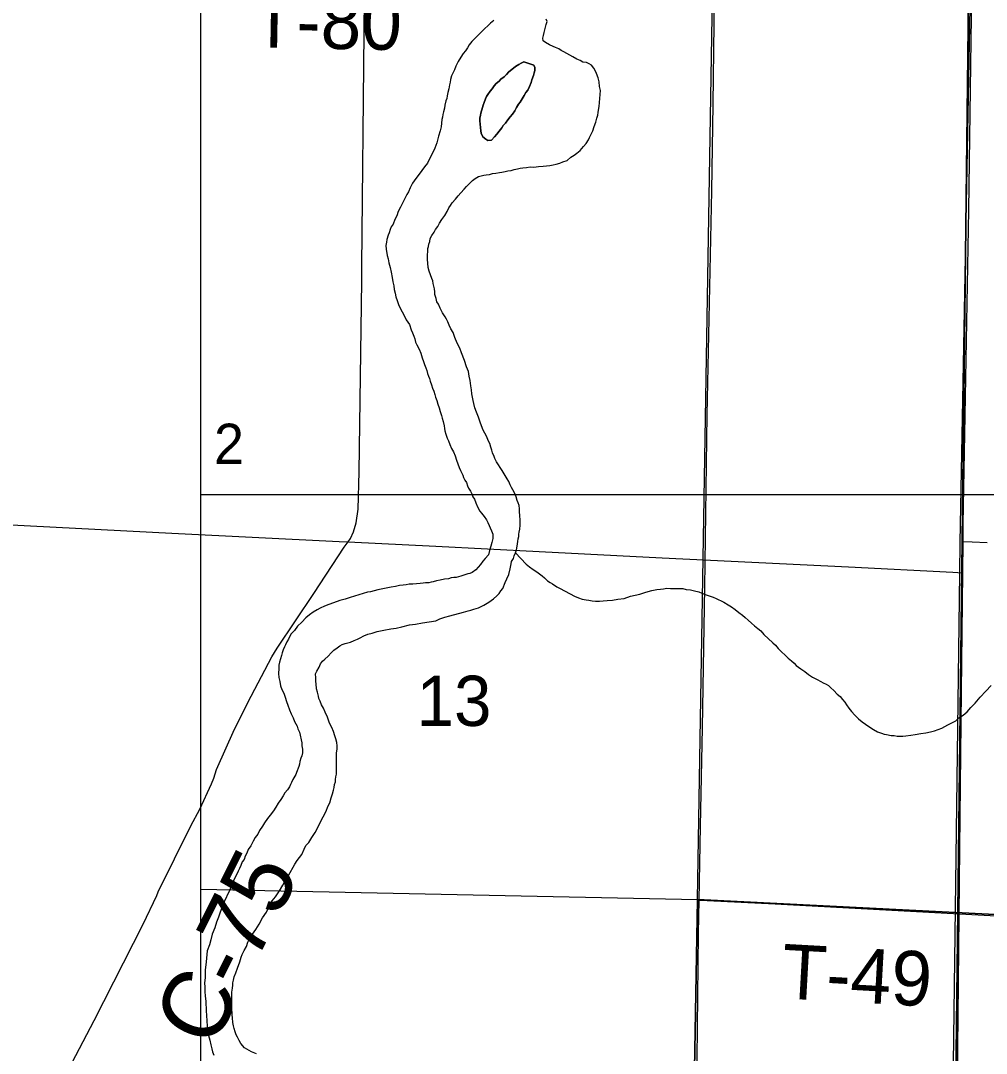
# Model space of a CAD drawing. Extents: x 0 to 68, y 0 to 52.9.
# Drawn here: x 42.06 to 43.122, y 34.125 to 35.26 of the extents above; entities that cross this region are included whole.
import ezdxf

# ---------------------------------------------------------------- set-up
doc = ezdxf.new("R2010")
doc.units = 0
for name, color, linetype in [('Default', 7, 'Continuous'), ('GM_X_County_Road', 7, 'Continuous'), ('GM_X_County_Road_Text', 7, 'Continuous'), ('GM_X_Minor_River', 7, 'Continuous'), ('GM_X_Township', 7, 'Continuous'), ('GM_X_Township_Road', 7, 'Continuous'), ('GM_X_Township_Road_Text', 7, 'Continuous')]:
    doc.layers.add(name, color=color, linetype=linetype)

msp = doc.modelspace()

# ---------------------------------------------------------------- linework, layer by layer
at = {"layer": 'Default'}
for p, q in [((42.2581, 31.1431), (42.2581, 38.5351)), ((42.2581, 34.7391), (49.6501, 34.7391))]:
    msp.add_line(p, q, dxfattribs=at)
for points in [[(43.089, 34.0291), (43.0906, 34.1657), (43.0925, 34.3503), (43.0942, 34.5226), (43.0956, 34.6532), (43.096, 34.6875), (43.0962, 34.7071), (43.0981, 34.8056), (43.1022, 35.0517), (43.1053, 35.2649), (43.1059, 35.3134), (43.1062, 35.3458), (43.1075, 35.4536), (43.1091, 35.5889), (43.1114, 35.8842), (43.1128, 36.0132), (43.1137, 36.1016), (43.1169, 36.3846), (43.1196, 36.6143), (43.12, 36.643), (43.1213, 36.7456), (43.1227, 36.8522)], [(42.2581, 34.3055), (42.8041, 34.2941), (42.7855, 33.2374), (42.2581, 33.2485)]]:
    msp.add_lwpolyline(points, dxfattribs=at)
for points in [[(41.7644, 35.3862), (43.1022, 35.3161), (43.0873, 34.0306), (43.0864, 33.9961), (41.7454, 34.0552)], [(43.1026, 35.3466), (43.6933, 35.3509), (44.3202, 35.3382), (44.3032, 34.0046), (43.0873, 34.0306), (43.1022, 35.3161)], [(42.821, 35.3089), (43.8802, 35.2907), (43.8665, 34.2714), (43.8657, 34.2406), (42.8041, 34.2941)], [(42.8041, 34.2941), (43.8657, 34.2406), (43.8561, 33.2057), (43.8558, 33.1813), (42.7855, 33.2374)]]:
    msp.add_lwpolyline(points, close=True, dxfattribs=at)
at = {"layer": 'GM_X_County_Road'}
for points in [[(42.4198, 34.6871), (42.4225, 34.6909), (42.426, 34.6983), (42.4289, 34.7082), (42.4308, 34.7233), (42.4322, 34.7643), (42.4349, 34.9736), (42.4349, 34.9899), (42.4376, 35.2473), (42.4382, 35.3252), (42.4389, 35.3376), (42.4396, 35.3493)], [(41.5874, 34.7233), (41.6335, 34.7225), (41.7192, 34.7213), (41.7888, 34.7191), (41.8706, 34.7152), (41.9361, 34.7118), (42.2262, 34.6969), (42.4102, 34.6875), (42.4198, 34.6871)], [(42.0801, 34.0424), (42.0847, 34.0517), (42.1085, 34.0993), (42.1406, 34.1609), (42.1946, 34.267), (42.2097, 34.2984), (42.2109, 34.3024), (42.247, 34.3749), (42.2567, 34.3933), (42.2698, 34.4213), (42.2724, 34.4273), (42.2753, 34.4371), (42.2951, 34.4811), (42.301, 34.4926), (42.3098, 34.5104), (42.336, 34.5607), (42.342, 34.5704), (42.3824, 34.6304), (42.4156, 34.6813), (42.4198, 34.6871)], [(42.4198, 34.6871), (42.5162, 34.6826), (42.6299, 34.6764), (42.7651, 34.6697), (42.9699, 34.6599), (43.0846, 34.6538), (43.0956, 34.6532)]]:
    msp.add_lwpolyline(points, dxfattribs=at)
at = {"layer": 'GM_X_Minor_River'}
for points in [[(42.637, 35.2362), (42.6345, 35.2378), (42.634, 35.2408), (42.6346, 35.2438), (42.6356, 35.2473), (42.6377, 35.2558), (42.6387, 35.2593), (42.6378, 35.2618)], [(42.58, 35.2604), (42.5764, 35.2575), (42.5734, 35.2545), (42.5703, 35.2515), (42.5673, 35.2485), (42.5648, 35.246), (42.5622, 35.2435), (42.5587, 35.2401), (42.5561, 35.2371), (42.5531, 35.2336), (42.551, 35.2301), (42.549, 35.2271), (42.5465, 35.2241), (42.5439, 35.2201), (42.5408, 35.2151), (42.5383, 35.2101), (42.5367, 35.2061), (42.5352, 35.2026), (42.5337, 35.1996), (42.5326, 35.1956), (42.5321, 35.1926), (42.5315, 35.1896), (42.5305, 35.1851), (42.5295, 35.1811), (42.5289, 35.1776), (42.5284, 35.1746), (42.5274, 35.1721), (42.5263, 35.1671), (42.5258, 35.164), (42.5247, 35.16), (42.5242, 35.157), (42.5237, 35.154), (42.5231, 35.1515), (42.5226, 35.1475), (42.5221, 35.1435), (42.521, 35.139), (42.5194, 35.133), (42.5174, 35.126), (42.5153, 35.1199), (42.5071, 35.1035), (42.504, 35.0995), (42.501, 35.0955), (42.4979, 35.0915), (42.4944, 35.0865), (42.4908, 35.0815), (42.4882, 35.0765), (42.4862, 35.072), (42.4846, 35.069), (42.4826, 35.0655), (42.4805, 35.061), (42.4775, 35.055), (42.4749, 35.0505), (42.4734, 35.0455), (42.4713, 35.0415), (42.4693, 35.0365), (42.4672, 35.0335), (42.4662, 35.0305), (42.4651, 35.027), (42.4641, 35.0245), (42.4626, 35.0195), (42.462, 35.0165), (42.4615, 35.013), (42.4619, 35.009), (42.4629, 35.0019), (42.4639, 34.9984), (42.4648, 34.9939), (42.4663, 34.9888), (42.4672, 34.9838), (42.4682, 34.9778), (42.4691, 34.9732)], [(42.5129, 34.9743), (42.5119, 34.9768), (42.5104, 34.9809), (42.5089, 34.9849), (42.508, 34.9889), (42.5075, 34.9934), (42.5071, 34.9975), (42.5071, 35), (42.5071, 35.003), (42.5076, 35.006), (42.5077, 35.0095), (42.5082, 35.012), (42.5087, 35.0145), (42.5098, 35.0175), (42.5103, 35.0205), (42.5118, 35.024), (42.5144, 35.0275), (42.5159, 35.0305), (42.5185, 35.034), (42.5205, 35.0375), (42.5231, 35.0415), (42.5261, 35.046), (42.5287, 35.0505), (42.5307, 35.0545), (42.5323, 35.057), (42.5343, 35.06), (42.5378, 35.064), (42.5409, 35.0674), (42.5439, 35.0709), (42.5475, 35.0749), (42.55, 35.0779), (42.5526, 35.0804), (42.5566, 35.0844), (42.5597, 35.0868), (42.5632, 35.0888), (42.5693, 35.0903), (42.5718, 35.0907), (42.5753, 35.0912), (42.5788, 35.0922), (42.5823, 35.0926), (42.5864, 35.0931), (42.5889, 35.0936), (42.5924, 35.0945), (42.5954, 35.095), (42.599, 35.0955), (42.6025, 35.0964), (42.606, 35.0974), (42.609, 35.0979), (42.612, 35.0983), (42.6161, 35.0988), (42.6201, 35.0993), (42.6241, 35.0992), (42.6291, 35.0997), (42.6342, 35.1001), (42.6382, 35.1006), (42.6417, 35.1011), (42.6452, 35.1015), (42.6488, 35.1025), (42.6528, 35.1034), (42.6558, 35.1049), (42.6609, 35.1064), (42.6649, 35.1099), (42.6685, 35.1123), (42.6715, 35.1143), (42.675, 35.1173), (42.6786, 35.1218), (42.6816, 35.1252), (42.6842, 35.1292), (42.6852, 35.1317), (42.6873, 35.1352), (42.6888, 35.1392), (42.6904, 35.1437), (42.6924, 35.1487), (42.6935, 35.1528), (42.6945, 35.1563), (42.695, 35.1593), (42.6951, 35.1618), (42.6961, 35.1658), (42.6972, 35.1788), (42.6973, 35.1834), (42.6963, 35.1879), (42.6959, 35.1929), (42.6949, 35.1974), (42.693, 35.202), (42.692, 35.2045), (42.69, 35.208), (42.6875, 35.2111), (42.685, 35.2126), (42.682, 35.2142), (42.678, 35.2147), (42.675, 35.2162), (42.6715, 35.2178), (42.667, 35.2203), (42.6605, 35.2239), (42.657, 35.226), (42.654, 35.2275), (42.6515, 35.229), (42.648, 35.2306), (42.6455, 35.2316), (42.6415, 35.2337), (42.637, 35.2362)], [(42.6242, 35.2112), (42.6132, 35.2149), (42.6102, 35.2134), (42.6076, 35.2119), (42.6041, 35.2099), (42.6, 35.2065), (42.5965, 35.204), (42.594, 35.201), (42.5914, 35.1985), (42.5879, 35.196), (42.5859, 35.1936), (42.5828, 35.1911), (42.5803, 35.1886), (42.5782, 35.1851), (42.5762, 35.1826), (42.5737, 35.1791), (42.5721, 35.1766), (42.5711, 35.1741), (42.5695, 35.1701), (42.5685, 35.1671), (42.5675, 35.1646), (42.5659, 35.1586), (42.5654, 35.1561), (42.5649, 35.1531), (42.5648, 35.1501), (42.5657, 35.139), (42.5662, 35.1365), (42.5682, 35.1325), (42.5712, 35.1299)], [(42.6242, 35.2112), (42.6252, 35.2087), (42.6252, 35.2052), (42.6246, 35.2027), (42.6236, 35.1997), (42.622, 35.1952), (42.621, 35.1922), (42.6195, 35.1877), (42.6174, 35.1837), (42.6154, 35.1812), (42.6133, 35.1777), (42.6113, 35.1742), (42.6092, 35.1707), (42.6072, 35.1682), (42.6052, 35.1647), (42.6031, 35.1612), (42.6006, 35.1572), (42.598, 35.1543), (42.5955, 35.1513), (42.5929, 35.1473), (42.5904, 35.1448), (42.5889, 35.1423), (42.5858, 35.1388), (42.5833, 35.1353), (42.5807, 35.1323), (42.5777, 35.1288), (42.5737, 35.1284), (42.5712, 35.1299), (42.5682, 35.1325), (42.5662, 35.1365), (42.5657, 35.139), (42.5648, 35.1501), (42.5649, 35.1531), (42.5654, 35.1561), (42.5659, 35.1586), (42.5675, 35.1646), (42.5685, 35.1671), (42.5695, 35.1701), (42.5711, 35.1741), (42.5721, 35.1766), (42.5737, 35.1791), (42.5762, 35.1826), (42.5782, 35.1851), (42.5803, 35.1886), (42.5828, 35.1911), (42.5859, 35.1936), (42.5879, 35.196), (42.5914, 35.1985), (42.594, 35.201), (42.5965, 35.204), (42.6, 35.2065), (42.6041, 35.2099), (42.6076, 35.2119), (42.6102, 35.2134), (42.6132, 35.2149), (42.6242, 35.2112)], [(42.5712, 35.1299), (42.5737, 35.1284), (42.5777, 35.1288), (42.5807, 35.1323), (42.5833, 35.1353), (42.5858, 35.1388), (42.5889, 35.1423), (42.5904, 35.1448), (42.5929, 35.1473), (42.5955, 35.1513), (42.598, 35.1543), (42.6006, 35.1572), (42.6031, 35.1612), (42.6052, 35.1647), (42.6072, 35.1682), (42.6092, 35.1707), (42.6113, 35.1742), (42.6133, 35.1777), (42.6154, 35.1812), (42.6174, 35.1837), (42.6195, 35.1877), (42.621, 35.1922), (42.622, 35.1952), (42.6236, 35.1997), (42.6246, 35.2027), (42.6252, 35.2052), (42.6252, 35.2087), (42.6242, 35.2112)], [(42.4691, 34.9732), (42.4701, 34.9687), (42.4706, 34.9647), (42.4715, 34.9607), (42.4725, 34.9566), (42.474, 34.9526), (42.4754, 34.9481), (42.4779, 34.9425), (42.4808, 34.9375), (42.4838, 34.9314), (42.4873, 34.9263), (42.4892, 34.9203), (42.4907, 34.9168), (42.4922, 34.9132), (42.4931, 34.9102), (42.4941, 34.9067), (42.4956, 34.9036), (42.498, 34.8991), (42.5, 34.8946), (42.5015, 34.8895), (42.5029, 34.8855), (42.5039, 34.882), (42.5054, 34.8784), (42.5064, 34.8754), (42.5073, 34.8724), (42.5083, 34.8694), (42.5093, 34.8668), (42.5103, 34.8638), (42.5117, 34.8598), (42.5127, 34.8563), (42.5142, 34.8527), (42.5151, 34.8492), (42.5161, 34.8462), (42.5176, 34.8426), (42.5186, 34.8386), (42.52, 34.8346), (42.521, 34.8305), (42.5224, 34.826), (42.5234, 34.823), (42.5244, 34.8195), (42.5254, 34.8149), (42.5258, 34.8119), (42.5263, 34.8094), (42.5273, 34.8054), (42.5287, 34.8013), (42.5302, 34.7983), (42.5317, 34.7943), (42.5336, 34.7897), (42.5356, 34.7862), (42.5376, 34.7816), (42.539, 34.7771), (42.5405, 34.7731), (42.542, 34.769), (42.5435, 34.7655), (42.5459, 34.7605), (42.5469, 34.7579), (42.5484, 34.7549), (42.5499, 34.7524), (42.5513, 34.7489), (42.5523, 34.7463), (42.5543, 34.7428), (42.5558, 34.7398), (42.5572, 34.7367), (42.5587, 34.7342), (42.5602, 34.7302), (42.5622, 34.7256), (42.5646, 34.7211), (42.5666, 34.7186), (42.5696, 34.715), (42.5721, 34.7115), (42.5735, 34.7084), (42.5775, 34.6994), (42.5789, 34.6958), (42.5789, 34.6933), (42.5789, 34.6908), (42.5778, 34.6863), (42.5768, 34.6823), (42.5752, 34.6778), (42.5742, 34.6728), (42.5706, 34.6688), (42.5681, 34.6658), (42.5655, 34.6623), (42.563, 34.6593), (42.5605, 34.6563), (42.5564, 34.6534), (42.5539, 34.6524), (42.5514, 34.6519), (42.5484, 34.6509), (42.5438, 34.6495), (42.5388, 34.648), (42.5363, 34.648), (42.5333, 34.6476), (42.5302, 34.6466), (42.5257, 34.6461), (42.5212, 34.6452), (42.5171, 34.6442), (42.5136, 34.6433), (42.5111, 34.6428), (42.5086, 34.6423), (42.5051, 34.6423), (42.5025, 34.6419)], [(42.479, 34.5939), (42.4875, 34.5958), (42.4941, 34.5967), (42.5016, 34.5982), (42.5092, 34.5991), (42.5162, 34.6005), (42.5207, 34.6025), (42.5263, 34.6044), (42.5318, 34.6059), (42.5469, 34.6098), (42.552, 34.6112), (42.555, 34.6122), (42.558, 34.6132), (42.5631, 34.6146), (42.5691, 34.6176), (42.5747, 34.621), (42.5798, 34.6245), (42.5833, 34.628), (42.5858, 34.6304), (42.5879, 34.6334), (42.5899, 34.6359), (42.5925, 34.6424), (42.5945, 34.6464), (42.5966, 34.6514), (42.5982, 34.6574), (42.5992, 34.663), (42.5997, 34.6655), (42.6018, 34.669), (42.6023, 34.672), (42.6039, 34.675), (42.6049, 34.6785), (42.6059, 34.6825), (42.6065, 34.6875), (42.607, 34.6905), (42.6076, 34.693), (42.6076, 34.6955), (42.6081, 34.698), (42.6086, 34.701), (42.6092, 34.7056), (42.6092, 34.7111), (42.6088, 34.7161), (42.6083, 34.7201), (42.6084, 34.7236), (42.6079, 34.7272), (42.6069, 34.7302), (42.6059, 34.7327), (42.6045, 34.7367), (42.6025, 34.7418), (42.601, 34.7443), (42.5995, 34.7468), (42.5981, 34.7499), (42.5966, 34.7534), (42.5946, 34.7564), (42.5926, 34.76), (42.5892, 34.7655), (42.5832, 34.7751), (42.5813, 34.7787), (42.5803, 34.7812), (42.5788, 34.7852), (42.5778, 34.7878), (42.5769, 34.7913), (42.5759, 34.7953), (42.5744, 34.7978), (42.572, 34.8034), (42.5685, 34.81), (42.5656, 34.8175), (42.5631, 34.8241), (42.5612, 34.8296), (42.5592, 34.8347), (42.5582, 34.8392), (42.5573, 34.8427), (42.5568, 34.8462), (42.5558, 34.8498), (42.5554, 34.8543), (42.5549, 34.8588), (42.554, 34.8644), (42.553, 34.8694), (42.5521, 34.8744), (42.5501, 34.8795), (42.5477, 34.8865), (42.5447, 34.8951), (42.5428, 34.9001), (42.5398, 34.9057), (42.5374, 34.9118), (42.5354, 34.9173), (42.5329, 34.9213), (42.531, 34.9254), (42.5295, 34.9289), (42.528, 34.9319), (42.5265, 34.9345), (42.5236, 34.939), (42.5211, 34.9441), (42.5191, 34.9486), (42.5176, 34.9511), (42.5167, 34.9547), (42.5152, 34.9592), (42.5152, 34.9622), (42.5148, 34.9652), (42.5143, 34.9683), (42.5133, 34.9713), (42.5129, 34.9743)], [(42.6039, 34.675), (42.6158, 34.6628), (42.6193, 34.6597), (42.6233, 34.6567), (42.6273, 34.6541), (42.6303, 34.6521), (42.6333, 34.65), (42.6357, 34.6475), (42.6392, 34.6445), (42.6422, 34.6424), (42.6447, 34.6409), (42.6492, 34.6378), (42.6522, 34.6363), (42.6642, 34.6301), (42.6687, 34.6276), (42.6732, 34.6255), (42.6772, 34.624), (42.6817, 34.6234), (42.6847, 34.6229), (42.6883, 34.6223), (42.6918, 34.6218), (42.6963, 34.6218), (42.7003, 34.6222), (42.7048, 34.6227), (42.7104, 34.6231), (42.7164, 34.6241), (42.7234, 34.625), (42.7305, 34.6274), (42.7406, 34.6298), (42.7471, 34.6318), (42.7537, 34.6337), (42.7592, 34.6347), (42.7632, 34.6351), (42.7668, 34.6356), (42.7703, 34.6361), (42.7743, 34.636), (42.7788, 34.636), (42.7838, 34.6359), (42.7879, 34.6359), (42.7914, 34.6348), (42.7964, 34.6343), (42.8009, 34.6332), (42.8054, 34.6322), (42.8089, 34.6306), (42.8134, 34.6291), (42.8179, 34.6275), (42.8214, 34.6265), (42.8244, 34.6249), (42.8269, 34.6239), (42.8299, 34.6224), (42.8329, 34.6208), (42.8379, 34.6178), (42.8414, 34.6157), (42.8454, 34.6127), (42.8494, 34.6096), (42.8534, 34.6066), (42.8564, 34.604), (42.8599, 34.601), (42.8634, 34.5979), (42.8668, 34.5949), (42.8703, 34.5918), (42.8738, 34.5893), (42.8768, 34.5852), (42.8868, 34.5761), (42.8897, 34.5735), (42.8927, 34.57), (42.8967, 34.5659), (42.9002, 34.5629), (42.9037, 34.5593), (42.9072, 34.5563), (42.9102, 34.5537), (42.9126, 34.5512), (42.9176, 34.5476), (42.9221, 34.5446), (42.9261, 34.5415), (42.9306, 34.5384), (42.9356, 34.5359), (42.9396, 34.5338), (42.9421, 34.5323), (42.9456, 34.5308), (42.9481, 34.5292), (42.9506, 34.5267), (42.9541, 34.5236), (42.9575, 34.5196), (42.961, 34.517), (42.9635, 34.514), (42.966, 34.511), (42.968, 34.5079), (42.9705, 34.5044), (42.9734, 34.5008), (42.9769, 34.4968), (42.9809, 34.4927), (42.9849, 34.4892), (42.9889, 34.4866), (42.9924, 34.4841), (42.9974, 34.481), (43.0019, 34.4784), (43.0064, 34.4769), (43.0094, 34.4758), (43.0119, 34.4753), (43.0169, 34.4743)], [(42.5025, 34.6419), (42.499, 34.6414), (42.495, 34.6409), (42.491, 34.6405), (42.487, 34.6405), (42.4839, 34.64), (42.4804, 34.6396), (42.4764, 34.6391), (42.4719, 34.6382), (42.4673, 34.6372), (42.4527, 34.6343), (42.4487, 34.6334), (42.4447, 34.6324), (42.4412, 34.632), (42.4366, 34.6305), (42.4316, 34.629), (42.427, 34.6276), (42.422, 34.6261), (42.4165, 34.6242), (42.4109, 34.6227), (42.4039, 34.6203), (42.3988, 34.6183), (42.3938, 34.6164), (42.3892, 34.6144), (42.3857, 34.6124), (42.3816, 34.61), (42.3776, 34.607), (42.3735, 34.6035), (42.369, 34.599), (42.3644, 34.5946), (42.3608, 34.5896), (42.3568, 34.5856), (42.3542, 34.5801), (42.3527, 34.5771), (42.3511, 34.5741), (42.3501, 34.5716), (42.3486, 34.5686), (42.3475, 34.5651), (42.3465, 34.5621), (42.3455, 34.5586), (42.3444, 34.5551), (42.3439, 34.5516), (42.3439, 34.5481), (42.3433, 34.5426), (42.3438, 34.538), (42.3447, 34.5335), (42.3457, 34.529), (42.3471, 34.5249), (42.3491, 34.5209), (42.3506, 34.5164), (42.352, 34.5118), (42.3535, 34.5078), (42.3555, 34.5027), (42.3574, 34.4982), (42.3594, 34.4937), (42.3609, 34.4896), (42.3623, 34.4871), (42.3638, 34.4846), (42.3648, 34.4815), (42.3663, 34.478), (42.3692, 34.4664), (42.3691, 34.4629), (42.3696, 34.4594), (42.3696, 34.4554), (42.369, 34.4519), (42.368, 34.4494), (42.367, 34.4459), (42.3664, 34.4429), (42.3659, 34.4403), (42.3633, 34.4338), (42.3623, 34.4313), (42.3592, 34.4258), (42.3577, 34.4228), (42.3567, 34.4203), (42.3556, 34.4178), (42.3531, 34.4144), (42.3505, 34.4114), (42.3485, 34.4079), (42.346, 34.4039), (42.3429, 34.3999), (42.3403, 34.3954), (42.3378, 34.3914), (42.3342, 34.3869), (42.3312, 34.3829), (42.3281, 34.3784), (42.3256, 34.3745), (42.3225, 34.37), (42.3205, 34.366), (42.3179, 34.362), (42.3154, 34.358), (42.3128, 34.353), (42.3102, 34.349), (42.3087, 34.345), (42.3066, 34.3415), (42.3056, 34.338), (42.3036, 34.3355), (42.302, 34.3315), (42.3005, 34.328), (42.299, 34.325), (42.2969, 34.3205), (42.2954, 34.318)], [(42.2921, 34.192), (42.2927, 34.1965), (42.2932, 34.2), (42.2932, 34.2025), (42.2938, 34.2055), (42.2948, 34.209), (42.2963, 34.2135), (42.2984, 34.2185), (42.301, 34.2255), (42.3025, 34.2305), (42.3036, 34.2335), (42.3056, 34.238), (42.3082, 34.2425), (42.3097, 34.247), (42.3118, 34.2515), (42.3148, 34.256), (42.3184, 34.261), (42.322, 34.267), (42.3256, 34.274), (42.3302, 34.28), (42.3338, 34.288), (42.3363, 34.2925), (42.3399, 34.297), (42.3445, 34.3034), (42.348, 34.3099), (42.3511, 34.3154), (42.3542, 34.3204), (42.3613, 34.3329), (42.3639, 34.3369), (42.369, 34.3434), (42.3715, 34.3494), (42.3736, 34.3534), (42.3766, 34.3568), (42.3802, 34.3623), (42.3838, 34.3678), (42.3869, 34.3738), (42.3894, 34.3793), (42.3925, 34.3848), (42.3956, 34.3913), (42.3976, 34.3963), (42.3997, 34.4003), (42.4012, 34.4058), (42.4028, 34.4103), (42.4038, 34.4143), (42.4044, 34.4173), (42.4049, 34.4203), (42.4059, 34.4234), (42.406, 34.4259), (42.4065, 34.4289), (42.407, 34.4319), (42.4071, 34.4349), (42.4071, 34.4384), (42.4071, 34.4434), (42.4072, 34.4469), (42.4072, 34.4505), (42.4073, 34.455), (42.4078, 34.4595), (42.4078, 34.463), (42.4074, 34.4665), (42.4064, 34.4706), (42.4054, 34.4741), (42.404, 34.4786), (42.402, 34.4832), (42.3995, 34.4877), (42.3971, 34.4943), (42.3946, 34.4998), (42.3927, 34.5044), (42.3907, 34.5079), (42.3892, 34.5119), (42.3877, 34.515), (42.3873, 34.5175), (42.3863, 34.522), (42.3853, 34.5255), (42.3849, 34.5311), (42.3844, 34.5336), (42.3845, 34.5376), (42.384, 34.5421), (42.3855, 34.5451), (42.3881, 34.5496), (42.3896, 34.5531), (42.3917, 34.5561), (42.3942, 34.5581), (42.3978, 34.5616), (42.4013, 34.5651), (42.4043, 34.568), (42.4079, 34.5705), (42.4109, 34.573), (42.4135, 34.5745), (42.4165, 34.5754), (42.4225, 34.5769), (42.4266, 34.5789), (42.4301, 34.5803), (42.4331, 34.5818), (42.4372, 34.5838), (42.4417, 34.5857), (42.4462, 34.5867), (42.4518, 34.5886), (42.4593, 34.5901), (42.4669, 34.5915), (42.4729, 34.5924), (42.479, 34.5939)], [(43.0169, 34.4743), (43.0204, 34.4742), (43.0234, 34.4737), (43.0264, 34.4737), (43.0299, 34.4736), (43.033, 34.4741), (43.0385, 34.4745), (43.0435, 34.4755), (43.0496, 34.4764), (43.0551, 34.4774), (43.0601, 34.4783), (43.0647, 34.4793), (43.0727, 34.4822), (43.0758, 34.4842), (43.0793, 34.4862), (43.0844, 34.4886), (43.0879, 34.4906), (43.0914, 34.4936), (43.096, 34.4965), (43.1006, 34.5005), (43.1046, 34.505), (43.1092, 34.51), (43.1148, 34.5164), (43.1209, 34.5229), (43.127, 34.5294)], [(42.2954, 34.318), (42.2938, 34.3145), (42.2918, 34.3095), (42.2897, 34.3045), (42.283, 34.29), (42.281, 34.285), (42.2794, 34.28), (42.2774, 34.2745), (42.2753, 34.269), (42.2732, 34.263), (42.2706, 34.256), (42.2691, 34.2495), (42.2675, 34.244), (42.2649, 34.2375), (42.2638, 34.2254), (42.2627, 34.2164), (42.2626, 34.2078), (42.2621, 34.2023), (42.2625, 34.1978), (42.2625, 34.1928), (42.2629, 34.1877), (42.2634, 34.1822), (42.2633, 34.1782), (42.2638, 34.1752), (42.2638, 34.1717), (42.2642, 34.1666), (42.2647, 34.1606), (42.2651, 34.1546), (42.2656, 34.15), (42.2665, 34.1445), (42.268, 34.1395), (42.2689, 34.1344), (42.2699, 34.1299), (42.2709, 34.1264), (42.2723, 34.1228)], [(42.3191, 34.1244), (42.3136, 34.1264), (42.3086, 34.1295), (42.3061, 34.131), (42.3021, 34.1356), (42.3001, 34.1391), (42.2982, 34.1427), (42.2967, 34.1452), (42.2957, 34.1487), (42.2947, 34.1522), (42.2938, 34.1553), (42.2933, 34.1588), (42.2928, 34.1638), (42.2924, 34.1673), (42.2919, 34.1754), (42.292, 34.1809), (42.2921, 34.1864), (42.2921, 34.192)]]:
    msp.add_lwpolyline(points, dxfattribs=at)
at = {"layer": 'GM_X_Township'}
msp.add_lwpolyline([(43.0644, 32.7683), (43.0839, 33.9959), (43.0844, 34.0287), (43.0925, 34.6527), (43.0929, 34.6864), (43.1046, 35.3142), (43.1053, 35.3456), (43.1113, 36.0138), (43.1191, 36.6427), (43.1235, 37.0176), (43.1252, 37.2584), (43.1291, 37.4252), (43.1246, 37.4931), (43.125, 37.5147), (43.132, 37.8314), (43.1321, 37.8584), (43.1323, 37.9511), (43.3145, 37.9477), (43.3203, 37.9479), (44.1214, 37.9431), (44.7776, 37.9316), (45.7636, 37.9078)], dxfattribs=at)
at = {"layer": 'GM_X_Township_Road'}
for points in [[(42.806, 34.2933), (42.8074, 34.3745), (42.8095, 34.4828), (42.8109, 34.5713), (42.8122, 34.6369), (42.8146, 34.827), (42.8197, 35.0729), (42.8212, 35.1681), (42.8222, 35.2566), (42.8229, 35.2959), (42.8231, 35.3092)], [(43.096, 34.6875), (43.1061, 34.6871), (43.1226, 34.6864)], [(42.7913, 33.235), (42.7914, 33.2429), (42.7918, 33.2987), (42.7934, 33.4102), (42.7967, 33.6267), (42.7984, 33.7481), (42.8, 33.899), (42.8038, 34.1187), (42.8053, 34.2565), (42.806, 34.2933)], [(42.806, 34.2933), (42.8145, 34.2929), (42.8894, 34.2893), (43.3354, 34.2651)]]:
    msp.add_lwpolyline(points, dxfattribs=at)

# ---------------------------------------------------------------- texts
at = {"layer": 'Default'}
for s, height, p in [('2', 0.0442, (42.2725, 34.7729)), ('13', 0.05525, (42.4953, 34.4848))]:
    msp.add_text(s, height=height, rotation=0, dxfattribs=at).set_placement(p)
at = {"layer": 'GM_X_County_Road_Text'}
msp.add_text('C-75', height=0.075, rotation=63.5877, dxfattribs=at).set_placement((42.2706, 34.1278))
at = {"layer": 'GM_X_Township_Road_Text'}
for s, rotation, p in [('T-80', 358.9386, (42.3136, 35.2308)), ('T-49', 356.8205, (42.8954, 34.1854))]:
    msp.add_text(s, height=0.06, rotation=rotation, dxfattribs=at).set_placement(p)

doc.saveas('drawing.dxf')
